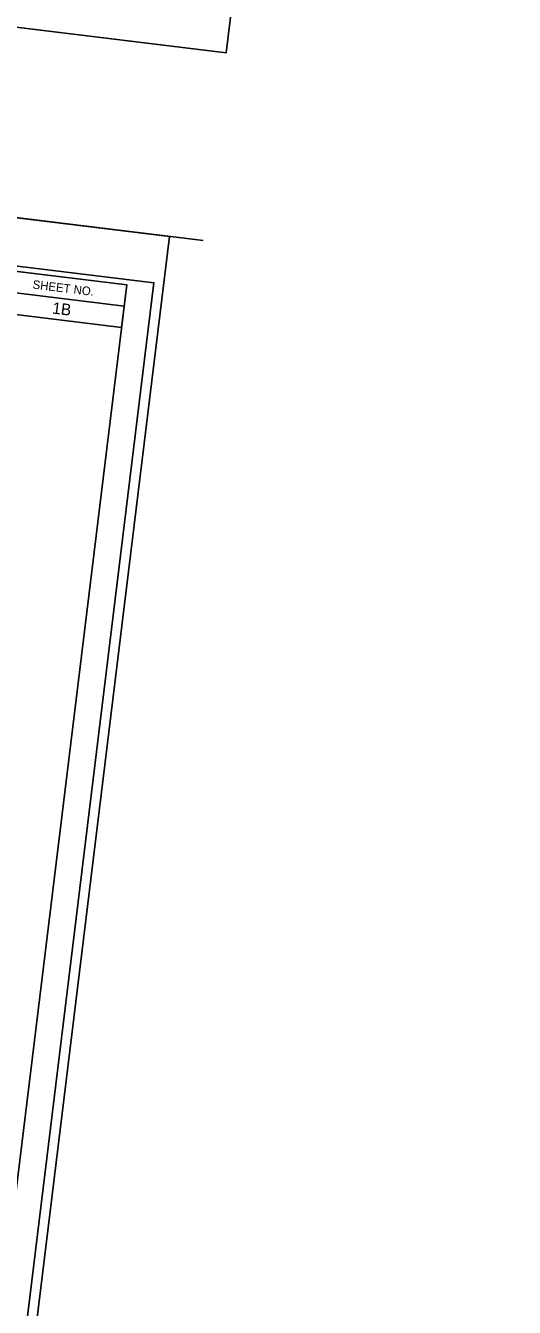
# Model space of a CAD drawing. Extents: x 1756435 to 1766932, y 416863 to 426859.
# Drawn here: x 1765661 to 1766576, y 419274 to 421675 of the extents above; entities that cross this region are included whole.
import ezdxf

# ---------------------------------------------------------------- set-up
doc = ezdxf.new("R2010")
doc.units = 0
for name, color, linetype in [('Scratch_Level_2', 7, 'Continuous'), ('Sheet Cutting Line CELL', 7, 'Continuous'), ('Sheet Data Field CELL', 7, 'Continuous'), ('Sheet Plot Border Inside CELL', 7, 'Continuous'), ('Sheet Plot Border Outside CELL', 7, 'Continuous'), ('Sheet Symbology CELL', 7, 'Continuous')]:
    doc.layers.add(name, color=color, linetype=linetype)

msp = doc.modelspace()

# ---------------------------------------------------------------- linework, layer by layer
at = {"layer": 'Scratch_Level_2'}
msp.add_lwpolyline([(1759243.8, 422098.1), (1765929.9, 421280), (1765395.5, 416912.5), (1758709.3, 417730.7)], close=True, dxfattribs=at)
at = {"layer": 'Sheet Cutting Line CELL'}
for p, q in [((1759286.8, 422449.7), (1766036.5, 421623.8)), ((1765993.4, 421272.2), (1759243.8, 422098.1)), ((1765929.9, 421280), (1759243.8, 422098.1))]:
    msp.add_line(p, q, dxfattribs=at)
at = {"layer": 'Sheet Plot Border Inside CELL'}
msp.add_lwpolyline([(1758771.9, 417813.5), (1765388.5, 417003.9), (1765901.1, 421193), (1759284.5, 422002.7)], close=True, dxfattribs=at)
at = {"layer": 'Sheet Plot Border Outside CELL'}
for points in [[(1766576, 426032.6), (1759826.3, 426858.6), (1759286.8, 422449.7), (1766036.5, 421623.8)], [(1758709.3, 417730.7), (1765395.5, 416912.5), (1765929.9, 421280), (1759243.8, 422098.1)]]:
    msp.add_lwpolyline(points, close=True, dxfattribs=at)
at = {"layer": 'Sheet Symbology CELL'}
for p, q in [((1765210, 421226.9), (1765845.4, 421149.1)), ((1765205.1, 421187.2), (1765840.5, 421109.4))]:
    msp.add_line(p, q, dxfattribs=at)
for points in [[(1765850.3, 421189), (1759894.7, 421917.7), (1759385, 417752.9), (1765340.6, 417024.1)], [(1765214.9, 421266.7), (1765850.3, 421189), (1765840.5, 421109.4), (1765205.1, 421187.2)]]:
    msp.add_lwpolyline(points, close=True, dxfattribs=at)

# ---------------------------------------------------------------- texts
at = {"layer": 'Sheet Data Field CELL'}
msp.add_text('1B', height=21.6, rotation=353.0234, dxfattribs=at).set_placement((1765709.8, 421135.5))
at = {"layer": 'Sheet Symbology CELL'}
msp.add_text('SHEET NO.', height=16, rotation=353.0234, dxfattribs=at).set_placement((1765673.1, 421182.3))

doc.saveas('drawing.dxf')
